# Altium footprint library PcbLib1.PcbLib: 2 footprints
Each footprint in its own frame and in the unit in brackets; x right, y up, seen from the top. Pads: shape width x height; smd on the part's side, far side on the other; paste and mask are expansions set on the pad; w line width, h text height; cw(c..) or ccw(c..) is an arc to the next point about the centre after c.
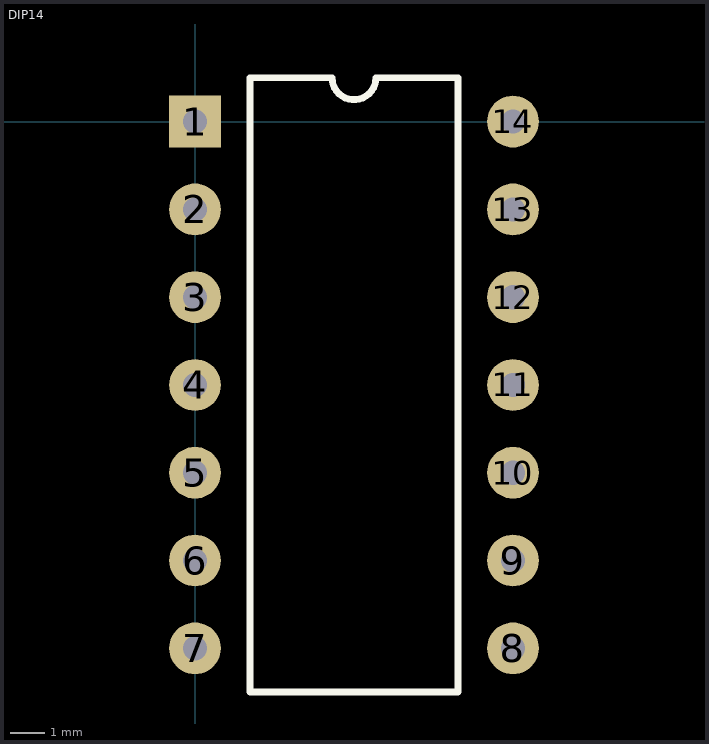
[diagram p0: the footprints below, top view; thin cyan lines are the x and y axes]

## DIP14 [mm]
pads (14):
  rect 1.5x1.5 hole 0.7: 1(0,0)
  round 1.5 hole 0.7: 2(0,-2.54) 3(0,-5.08) 4(0,-7.62) 5(0,-10.16) 6(0,-12.7) 7(0,-15.24) 8(9.2,-15.24) 9(9.2,-12.7) 10(9.2,-10.16) 11(9.2,-7.62) 12(9.2,-5.08) 13(9.2,-2.54) 14(9.2,0)
Top Overlay:
  lines w0.2: 1.585,-16.51 1.585,1.27 3.965,1.27 ccw(c4.6,1.27) 5.235,1.27 7.615,1.27 7.615,-16.51 1.585,-16.51

## PCBComponent_1 [mm]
